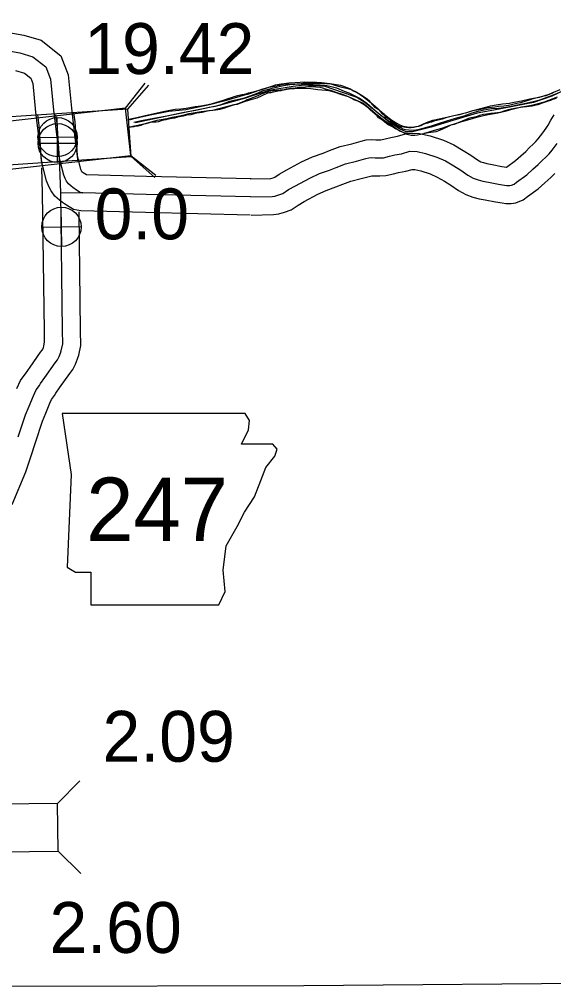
# Model space of a CAD drawing. Extents: x -83719 to 153526, y -11835 to 11446.
# Drawn here: x -1341.3 to -1193.4, y -29.8 to 238 of the extents above; entities that cross this region are included whole.
import ezdxf

# ---------------------------------------------------------------- set-up
doc = ezdxf.new("R2010")
doc.units = 0
for name, color, linetype in [('Level 10', 7, 'Continuous'), ('Level 2', 7, 'Continuous'), ('Level 20', 7, 'Continuous'), ('Level 21', 7, 'Continuous'), ('Level 25', 7, 'Continuous'), ('Level 26', 7, 'Continuous'), ('Level 58', 7, 'Continuous'), ('Level 59', 7, 'Continuous'), ('Level 9', 7, 'Continuous')]:
    doc.layers.add(name, color=color, linetype=linetype)

msp = doc.modelspace()

# ---------------------------------------------------------------- linework, layer by layer
at = {"layer": 'Level 10'}
for points in [[(-1364.45, 238.05), (-1340.09, 233.63), (-1335.27, 232.25), (-1329.85, 227.95), (-1327.78, 222.66), (-1326.9, 213.41), (-1325.93, 205.24), (-1325.18, 198.7)], [(-1342.37, 223.88), (-1339.93, 223.18), (-1338.17, 221.79), (-1337.6, 220.32), (-1336.85, 212.35), (-1335.86, 204.08), (-1335.14, 197.78)], [(-1277.17, 193.85), (-1306.13, 194.52), (-1322.78, 194.95), (-1322.78, 194.96), (-1323.66, 195.54), (-1323.86, 195.69), (-1323.95, 195.77), (-1324, 195.84), (-1324.16, 196.13), (-1324.31, 196.49), (-1325.27, 200.31), (-1325.89, 209.67), (-1326.24, 212.25)], [(-1277.41, 183.85), (-1306.38, 184.53), (-1324.28, 184.99), (-1326.37, 185.37), (-1328.27, 186.6), (-1329.4, 187.35), (-1330.19, 187.93), (-1331.51, 189.12), (-1332.52, 190.58), (-1333.16, 191.76), (-1333.81, 193.28), (-1335.19, 198.74), (-1335.85, 208.67), (-1336.24, 211.56)], [(-1277.4, 193.85), (-1271.81, 193.97), (-1271.7, 193.99), (-1271.01, 194.19), (-1270.64, 194.32), (-1269.4, 195.17), (-1267.24, 196.34), (-1263.2, 198.56), (-1260.15, 199.97), (-1257.2, 200.98), (-1255.46, 201.71), (-1252.53, 202.81), (-1249.23, 203.61), (-1246.7, 204.31), (-1245.33, 204.65), (-1243.84, 204.76), (-1242.61, 204.67), (-1241.8, 204.67), (-1241.23, 204.7), (-1240.04, 204.98), (-1238.45, 205.37), (-1236.64, 205.71), (-1233.78, 206.53), (-1230.58, 206.39), (-1227.59, 205.75), (-1223.92, 204.59), (-1221.07, 203.26), (-1218.47, 201.76), (-1216.36, 200.44), (-1214.51, 199.16), (-1213.56, 198.63), (-1212.82, 198.36), (-1211.93, 198.13), (-1210.44, 197.86), (-1207.76, 197.31), (-1206.44, 197.11), (-1203.94, 198.94), (-1202.44, 200.26), (-1201.12, 201.43), (-1200.07, 202.51), (-1199.03, 203.5), (-1198.28, 204.21), (-1197.71, 204.91), (-1196.41, 206.64), (-1195.44, 207.93), (-1194.92, 208.71), (-1194.2, 210.13), (-1193.27, 211.63)], [(-1342.04, 135.83), (-1340.98, 138.04), (-1339.96, 139.37), (-1339.68, 139.88), (-1338.36, 141.73), (-1335.45, 145.87), (-1335, 146.47), (-1334.88, 146.7), (-1334.69, 147.2), (-1334.59, 147.53), (-1334.33, 148.73), (-1334.36, 151.78), (-1334.89, 189.98), (-1335.14, 196.89)], [(-1277.18, 183.85), (-1270.92, 183.98), (-1269.5, 184.21), (-1267.94, 184.67), (-1266.07, 185.33), (-1264.17, 186.63), (-1262.45, 187.56), (-1258.68, 189.63), (-1256.4, 190.69), (-1253.67, 191.63), (-1251.79, 192.4), (-1249.57, 193.24), (-1246.72, 193.93), (-1244.15, 194.64), (-1243.78, 194.73), (-1242.98, 194.68), (-1241.53, 194.67), (-1239.83, 194.77), (-1237.72, 195.25), (-1236.33, 195.6), (-1234.35, 195.96), (-1232.59, 196.47), (-1231.85, 196.44), (-1230.15, 196.07), (-1227.56, 195.25), (-1225.69, 194.38), (-1223.62, 193.19), (-1221.86, 192.08), (-1219.78, 190.65), (-1217.75, 189.52), (-1215.79, 188.8), (-1214.06, 188.36), (-1212.34, 188.04), (-1209.52, 187.47), (-1207.69, 187.19), (-1206.65, 187.04), (-1205.16, 187.08), (-1203.83, 187.23), (-1201.82, 188.07), (-1200.67, 188.94), (-1197.69, 191.13), (-1195.81, 192.77), (-1194.2, 194.21), (-1193.04, 195.39)], [(-1343.29, 103.66), (-1339.58, 112.77), (-1338.2, 116.92), (-1336.87, 120.85), (-1334.96, 126.79), (-1334.04, 128.98), (-1332.89, 131.78), (-1332.42, 132.77), (-1331.58, 133.86), (-1331.2, 134.55), (-1330.19, 135.97), (-1327.37, 139.98), (-1326.56, 141.06), (-1325.75, 142.56), (-1325.21, 144), (-1324.91, 145.01), (-1324.31, 147.68), (-1324.36, 151.9), (-1324.81, 184.72)]]:
    msp.add_lwpolyline(points, dxfattribs=at)
at = {"layer": 'Level 2'}
for points in [[(-1188.22, 219.49), (-1193.88, 216.8), (-1198.99, 215), (-1209.97, 212.91), (-1214.57, 212.06), (-1222.24, 209.75), (-1227.33, 208.22), (-1232.5, 206.88), (-1234.26, 206.94), (-1236.08, 207.76), (-1238.53, 209.3), (-1245.71, 215.02), (-1247.92, 216.4), (-1248.86, 216.78), (-1256.63, 219.42), (-1258, 219.55), (-1260.07, 219.63), (-1262.47, 219.83), (-1265.53, 219.45), (-1272.23, 218.31), (-1277.97, 216.54)], [(-1277.68, 216.73), (-1276.17, 217.3), (-1275.06, 217.83), (-1273.84, 218.33), (-1272.38, 218.7), (-1270.92, 219.07), (-1269.77, 219.37), (-1268.24, 219.68), (-1266.48, 219.99), (-1263.66, 220.16), (-1262.22, 220.1), (-1260.02, 220.03), (-1258.02, 219.91), (-1256.68, 219.81), (-1255.41, 219.55), (-1253.56, 219.06), (-1251.44, 218.15), (-1250.13, 217.68), (-1248.77, 217.01), (-1246.95, 216.13), (-1245.12, 214.87), (-1243.51, 213.45), (-1241.7, 211.89), (-1241.22, 211.47), (-1240.27, 210.73), (-1239.39, 210.12), (-1238.1, 209.41), (-1237.39, 208.93), (-1236.51, 208.45), (-1235.8, 208.11), (-1235.12, 207.76), (-1234.38, 207.54), (-1233.48, 207.43), (-1232.21, 207.4), (-1230.92, 207.53), (-1229.56, 207.9), (-1227.18, 208.57), (-1225.56, 209.11), (-1222.99, 209.94), (-1220.61, 210.71), (-1218.19, 211.37), (-1215.95, 212.17), (-1214.3, 212.58), (-1212.74, 212.95), (-1210.62, 213.34), (-1208.62, 213.46), (-1206.56, 213.71), (-1205.14, 213.99), (-1202.98, 214.44), (-1201.59, 214.71), (-1199.07, 215.25), (-1197.22, 215.73), (-1195.14, 216.45), (-1193.46, 217.16), (-1191.68, 217.88)], [(-1309.2, 209.45), (-1299.09, 211.64), (-1285.9, 214.25), (-1277.97, 216.54)], [(-1297.95, 211.87), (-1295.69, 212.31), (-1294.09, 212.64), (-1292.49, 212.94), (-1288.76, 213.71), (-1287.03, 213.98), (-1285.43, 214.48), (-1283.07, 215.42), (-1281.97, 215.69), (-1281.01, 215.86), (-1279.41, 216.23), (-1278.68, 216.43), (-1277.68, 216.73)], [(-1309.68, 209.56), (-1307.54, 209.99), (-1305.14, 210.5), (-1302.54, 210.93), (-1300.51, 211.33), (-1297.95, 211.87)], [(-1136.66, -28.88), (-1174.76, -28.9), (-1262.54, -29.61)], [(-1262.54, -29.61), (-1343.7, -29.84)]]:
    msp.add_lwpolyline(points, dxfattribs=at)
at = {"layer": 'Level 20'}
for p, q in [((-1311.96, 213.45), (-1306.48, 220.34)), ((-1311.3, 213.21), (-1305.5, 219.83)), ((-1310.48, 200.34), (-1303.59, 194.86)), ((-1310.42, 200.04), (-1303.8, 194.24)), ((-1330.76, 20.89), (-1324.61, 27.18)), ((-1330.61, 7.69), (-1324.31, 1.54))]:
    msp.add_line(p, q, dxfattribs=at)
for points in [[(-1349.82, 195.87), (-1310.48, 200.34), (-1311.96, 213.45), (-1351.31, 208.98)], [(-1311.3, 213.21), (-1350.81, 210.58), (-1349.93, 197.41), (-1310.42, 200.04)], [(-1330.76, 20.89), (-1370.36, 20.43), (-1370.2, 7.23), (-1330.61, 7.69)]]:
    msp.add_lwpolyline(points, close=True, dxfattribs=at)
at = {"layer": 'Level 21'}
msp.add_lwpolyline([(-1329.49, 128.9), (-1326.95, 111.98), (-1328.08, 86.32), (-1325.82, 84.91), (-1321.59, 84.91), (-1321.59, 75.89), (-1286.06, 75.89), (-1284.37, 79.55), (-1284.94, 85.48), (-1284.09, 92.24), (-1280.99, 97.6), (-1279.02, 101.55), (-1276.2, 105.78), (-1274.5, 110.29), (-1273.09, 113.95), (-1270.56, 117.06), (-1269.99, 119.03), (-1271.12, 120.44), (-1279.86, 120.44), (-1277.89, 124.39), (-1277.61, 126.93), (-1278.78, 128.87)], close=True, dxfattribs=at)
at = {"layer": 'Level 26'}
for p, q in [((-1330.63, 200), (-1330.89, 210.85)), ((-1330.74, 198.37), (-1330.74, 209.2)), ((-1336.18, 205.3), (-1325.34, 205.55)), ((-1336.16, 203.78), (-1325.33, 203.78)), ((-1329.54, 175.15), (-1329.79, 186)), ((-1335.09, 180.45), (-1324.24, 180.7))]:
    msp.add_line(p, q, dxfattribs=at)
for centre, radius in [((-1330.76, 205.43), 5.43), ((-1330.74, 203.78), 5.42), ((-1329.66, 180.58), 5.43)]:
    msp.add_circle(centre, radius, dxfattribs=at)
at = {"layer": 'Level 59'}
for points in [[(-1364.89, 233.04), (-1341.23, 228.76), (-1337.6, 227.71), (-1334.01, 224.87), (-1332.69, 221.49), (-1331.87, 212.88), (-1330.89, 204.66), (-1330.16, 198.18)], [(-1277.29, 188.85), (-1306.25, 189.53), (-1323.76, 189.98), (-1324.5, 190.11), (-1325.53, 190.78), (-1326.53, 191.45), (-1327.03, 191.81), (-1327.73, 192.45), (-1328.26, 193.21), (-1328.66, 193.95), (-1329.06, 194.88), (-1330.23, 199.52), (-1330.87, 209.17), (-1331.2, 211.59)], [(-1277.29, 188.85), (-1271.36, 188.98), (-1270.6, 189.1), (-1269.48, 189.43), (-1268.35, 189.82), (-1266.78, 190.9), (-1264.85, 191.95), (-1260.94, 194.09), (-1258.27, 195.33), (-1255.44, 196.31), (-1253.62, 197.05), (-1251.05, 198.02), (-1247.97, 198.77), (-1245.43, 199.47), (-1244.53, 199.7), (-1243.83, 199.75), (-1242.8, 199.68), (-1241.67, 199.67), (-1240.53, 199.73), (-1238.88, 200.11), (-1237.39, 200.49), (-1235.5, 200.84), (-1233.18, 201.5), (-1231.22, 201.41), (-1228.87, 200.91), (-1225.74, 199.92), (-1223.38, 198.82), (-1221.04, 197.47), (-1219.11, 196.26), (-1217.14, 194.91), (-1215.65, 194.08), (-1214.31, 193.58), (-1213, 193.24), (-1211.39, 192.95), (-1208.64, 192.39), (-1206.97, 192.13), (-1206.37, 192.05), (-1205.5, 192.07), (-1205.1, 192.12), (-1204.34, 192.44), (-1203.66, 192.96), (-1200.82, 195.03), (-1199.12, 196.51), (-1197.66, 197.82), (-1196.56, 198.95), (-1195.58, 199.88), (-1194.61, 200.81), (-1193.77, 201.83), (-1192.42, 203.63)], [(-1341.62, 122.42), (-1339.66, 128.53), (-1338.66, 130.9), (-1337.46, 133.81), (-1336.7, 135.41), (-1335.77, 136.61), (-1335.44, 137.21), (-1334.27, 138.85), (-1331.41, 142.93), (-1330.78, 143.76), (-1330.32, 144.63), (-1329.95, 145.6), (-1329.75, 146.27), (-1329.32, 148.2), (-1329.36, 151.84), (-1329.89, 190.11), (-1330.23, 199.52)], [(-1329.89, 190.11), (-1323.76, 189.98)]]:
    msp.add_lwpolyline(points, dxfattribs=at)
at = {"layer": 'Level 9'}
for points in [[(-1277.88, 217.66), (-1276.26, 218.06), (-1275.24, 218.32), (-1274.15, 218.65), (-1273.02, 219.02), (-1272.3, 219.27), (-1271.47, 219.52), (-1270.38, 219.95), (-1268.86, 220.23), (-1268.03, 220.32), (-1266.73, 220.45), (-1264.93, 220.53), (-1263.6, 220.63), (-1262.44, 220.7), (-1260.67, 220.68), (-1259.04, 220.62), (-1257.7, 220.59), (-1256.8, 220.48), (-1255.39, 220.25), (-1253.68, 219.76), (-1252.07, 219.3), (-1250.76, 219), (-1249.48, 218.6), (-1247.9, 217.84), (-1246, 216.59), (-1243.89, 214.94), (-1242.83, 214), (-1240.85, 212.25), (-1240.23, 211.76), (-1240.09, 211.6), (-1238.56, 210.4), (-1237.75, 209.89), (-1236.97, 209.38), (-1236.16, 208.93), (-1235.31, 208.59), (-1234.51, 208.41), (-1233.34, 208.2), (-1232.54, 208.19), (-1231.57, 208.35), (-1230.85, 208.5), (-1229.46, 209.11), (-1228.57, 209.5), (-1226.89, 210.08), (-1225.07, 210.52), (-1222.58, 211.06), (-1220.2, 211.62), (-1217.42, 212.29), (-1216.06, 212.7), (-1213.95, 213.22), (-1212.19, 213.7), (-1210.9, 214.07), (-1209.31, 214.38), (-1207.52, 214.66), (-1205.59, 214.87), (-1204.37, 215.11), (-1202.31, 215.5), (-1200.03, 216.06), (-1197.94, 216.41), (-1196.09, 216.86), (-1194.63, 217.33), (-1192.66, 218.15)], [(-1253.61, 219.93), (-1254.75, 220.07), (-1256.28, 220.19), (-1257.42, 220.26), (-1259.18, 220.25), (-1260.55, 220.25), (-1262.88, 220.25), (-1263.74, 220.13), (-1264.54, 220.08), (-1265.14, 220.03), (-1265.54, 219.99), (-1266.01, 219.97), (-1266.41, 220), (-1266.57, 220.03), (-1267.18, 220.08), (-1267.64, 220.06), (-1268.67, 219.9), (-1269.27, 219.75), (-1269.95, 219.66)], [(-1191.72, 218.5), (-1193.47, 217.75), (-1193.93, 217.5), (-1194.45, 217.29), (-1195.54, 216.89), (-1196.11, 216.78), (-1197.36, 216.38), (-1199.12, 216), (-1199.88, 215.75), (-1202.56, 214.97), (-1203.58, 214.75), (-1204.28, 214.56), (-1205.04, 214.38), (-1205.93, 214.19), (-1207.23, 213.99), (-1208.63, 213.88), (-1209.72, 213.72), (-1211.42, 213.54), (-1212.34, 213.38), (-1213.57, 213.12), (-1214.7, 212.92), (-1215.86, 212.69), (-1217.48, 212.18), (-1218.6, 211.89), (-1219.59, 211.59), (-1221.05, 211.32), (-1223.2, 210.73), (-1224.26, 210.37), (-1225.35, 210.11), (-1226.58, 209.84), (-1227.24, 209.59), (-1227.73, 209.48), (-1228.26, 209.33), (-1229.06, 209.11), (-1229.48, 208.9), (-1230.21, 208.58), (-1230.77, 208.4), (-1231.33, 208.25), (-1232.09, 208.1), (-1232.83, 208.04), (-1233.53, 208.03), (-1234.29, 208.07), (-1235.5, 208.28), (-1236.2, 208.49), (-1236.88, 208.84), (-1237.59, 209.32), (-1238.27, 209.74), (-1238.68, 210.1), (-1239.77, 210.87), (-1240.25, 211.39), (-1240.66, 211.78), (-1241.24, 212.43), (-1241.65, 212.86), (-1242.16, 213.18), (-1242.78, 213.66), (-1243.49, 214.38), (-1244.15, 215.13), (-1244.32, 215.29), (-1245.04, 215.91), (-1245.85, 216.49), (-1246.39, 216.84), (-1247.34, 217.39), (-1248.32, 217.93), (-1249, 218.28), (-1249.85, 218.76), (-1250.59, 219.1), (-1251.46, 219.45), (-1252.3, 219.69), (-1253.61, 219.93)], [(-1310.98, 210.37), (-1309.73, 210.69), (-1308.77, 210.89), (-1306.47, 211.43), (-1304.37, 211.86), (-1302.34, 212.37), (-1301.01, 212.6), (-1299.18, 212.97), (-1298.15, 213.17), (-1296.62, 213.31), (-1295.19, 213.47), (-1292.66, 213.88), (-1291.06, 214.08), (-1289.5, 214.41), (-1287.83, 214.78), (-1286.03, 215.32), (-1284.3, 215.85), (-1283.54, 216.16), (-1282.31, 216.52), (-1281.84, 216.69), (-1280.81, 216.96), (-1279.74, 217.19), (-1279.08, 217.36), (-1278.55, 217.46), (-1277.88, 217.66)], [(-1278.11, 217.34), (-1284.73, 215.42), (-1288.66, 214.39), (-1295.26, 212.97), (-1299.92, 212.51), (-1305.11, 211.49), (-1309.98, 210.36), (-1310.96, 210.14)], [(-1278.11, 217.34), (-1275.95, 218.11), (-1274.21, 218.74), (-1272.24, 219.27), (-1269.95, 219.66)], [(-1272.63, 217.63), (-1275.59, 216.24), (-1276.93, 215.82), (-1277.91, 215.54)], [(-1277.58, 216.03), (-1275.2, 216.99), (-1274.31, 217.38), (-1272.96, 217.92), (-1272.27, 218.13), (-1271.04, 218.33), (-1270.07, 218.43), (-1269.14, 218.48), (-1267.61, 218.62), (-1266.12, 218.86), (-1265.12, 218.92), (-1263.16, 218.97), (-1261.86, 218.98), (-1260.59, 218.91), (-1258.68, 218.66), (-1256.51, 218.45), (-1255.64, 218.34), (-1254.27, 217.97), (-1252.18, 217.23), (-1250.33, 216.64), (-1248.61, 215.98), (-1246.18, 214.81), (-1244.14, 213.2), (-1242.06, 211.41), (-1242.02, 211.42), (-1240.9, 210.54), (-1239.2, 209.39), (-1238.05, 208.58), (-1236.45, 207.49), (-1235.13, 206.82), (-1234.26, 206.53)], [(-1192.69, 216.13), (-1193.68, 215.81), (-1194.28, 215.59), (-1194.9, 215.37), (-1196.55, 214.8), (-1197.74, 214.36), (-1198.6, 214.21), (-1199.33, 214.02), (-1200.16, 213.93), (-1200.93, 213.85), (-1201.86, 213.72), (-1202.55, 213.64), (-1203.02, 213.56), (-1203.71, 213.44), (-1204.18, 213.36), (-1205.17, 213.17), (-1205.97, 212.98), (-1206.6, 212.77), (-1207.16, 212.58), (-1207.42, 212.48), (-1207.88, 212.37), (-1208.25, 212.26), (-1208.98, 212.14), (-1209.74, 212.02), (-1210.74, 211.96), (-1212, 211.79), (-1212.83, 211.67), (-1213.89, 211.41), (-1214.88, 211.08), (-1216.7, 210.7), (-1217, 210.56), (-1217.59, 210.34), (-1220.26, 209.21), (-1220.92, 208.95), (-1221.85, 208.7), (-1222.93, 208.2), (-1223.99, 207.74), (-1225.01, 207.28), (-1226, 206.89), (-1228.69, 206.52), (-1229.32, 206.37), (-1230.28, 206.14), (-1231.07, 205.95), (-1231.87, 205.86), (-1232.8, 205.87), (-1233.24, 205.96), (-1233.97, 206.14), (-1234.62, 206.43), (-1235.23, 206.81), (-1236.03, 207.09), (-1236.54, 207.41), (-1237.39, 207.83), (-1237.86, 208.21), (-1238.54, 208.56), (-1239.25, 208.81), (-1241.08, 210.27), (-1241.9, 210.78), (-1242.25, 211.31), (-1243.44, 212.38), (-1244.22, 212.96), (-1244.71, 213.55), (-1245.52, 214.06), (-1246.33, 214.61), (-1247.08, 215.12), (-1247.62, 215.37), (-1248.7, 215.78), (-1249.24, 216.1), (-1249.98, 216.52), (-1250.83, 216.86), (-1252.14, 217.33), (-1253.32, 217.7), (-1254.39, 218.04), (-1255.2, 218.35), (-1256.61, 218.75), (-1257.32, 218.96), (-1258.12, 219.14), (-1259.26, 219.31), (-1260.29, 219.32), (-1261.49, 219.36), (-1262.22, 219.3), (-1263.22, 219.21), (-1263.92, 219.13), (-1264.95, 219.03), (-1265.91, 218.87), (-1266.44, 218.86), (-1267.07, 218.74), (-1267.44, 218.67), (-1267.97, 218.49), (-1268.96, 218.29), (-1269.42, 218.21), (-1270.15, 218.06), (-1270.58, 217.95), (-1271.05, 217.87), (-1271.68, 217.72), (-1272.31, 217.67), (-1272.57, 217.63), (-1272.63, 217.63)], [(-1311.23, 208.2), (-1309.43, 208.55), (-1307.7, 208.92), (-1306.14, 209.29), (-1304.51, 209.73), (-1303.17, 210.13), (-1302.08, 210.33), (-1300.51, 210.63), (-1298.98, 211), (-1297.95, 211.14), (-1296.55, 211.44), (-1295.32, 211.71), (-1294.32, 211.94), (-1292.69, 212.24), (-1290.96, 212.54), (-1289.53, 212.74), (-1288.7, 212.81), (-1287, 212.98), (-1285.77, 213.18), (-1284.4, 213.52), (-1283.47, 213.92), (-1282.3, 214.32), (-1281.07, 214.66), (-1279.71, 215.12), (-1278.74, 215.53), (-1278.21, 215.86), (-1277.58, 216.03)], [(-1277.91, 215.54), (-1278.78, 215.31), (-1280.11, 214.81), (-1281.07, 214.51), (-1281.94, 214.38), (-1284.34, 213.75), (-1287.9, 212.82), (-1288.83, 212.69), (-1289.6, 212.49), (-1290.67, 212.29), (-1291.46, 212.13), (-1292.2, 212.03), (-1292.9, 211.9), (-1293.86, 211.63), (-1295.09, 211.47), (-1295.99, 211.23), (-1296.96, 211.04), (-1297.83, 210.87), (-1298.39, 210.71), (-1299.06, 210.61), (-1300.16, 210.37), (-1300.79, 210.24), (-1301.39, 210.11), (-1302.09, 209.91), (-1302.85, 209.71), (-1303.49, 209.61), (-1304.02, 209.61), (-1304.62, 209.55), (-1305.35, 209.38), (-1306.28, 209.12), (-1306.88, 208.99), (-1307.68, 208.65), (-1308.48, 208.49), (-1308.98, 208.42), (-1309.68, 208.29), (-1310.41, 208.19), (-1310.7, 208.16)], [(-1229.34, 206.53), (-1228.79, 206.65), (-1226.38, 207.38), (-1224.33, 207.94), (-1222.09, 208.7), (-1220.57, 209.17), (-1218.16, 209.94), (-1215.87, 210.63), (-1214.65, 210.96), (-1212.8, 211.45), (-1211.54, 211.71), (-1209.32, 212.11), (-1207.99, 212.37), (-1206.47, 212.72), (-1205.54, 213.01), (-1204.85, 213.19), (-1203.36, 213.53), (-1202.33, 213.79), (-1201.07, 213.99), (-1199.55, 214.3), (-1197.66, 214.78), (-1195.91, 215.2), (-1192.28, 216.59)]]:
    msp.add_lwpolyline(points, dxfattribs=at)

# ---------------------------------------------------------------- texts
at = {"layer": 'Level 21'}
msp.add_text('247', height=17.6, dxfattribs=at).set_placement((-1322.82, 93.54))
at = {"layer": 'Level 25'}
for s, p in [('19.42', (-1323.38, 222.91)), ('0.0', (-1320.51, 177.13)), ('2.60', (-1333, -20.49))]:
    msp.add_text(s, height=14.08, dxfattribs=at).set_placement(p)
at = {"layer": 'Level 58'}
for s, p in [('0.0', (-1320.51, 177.13)), ('2.09', (-1318.32, 32.45))]:
    msp.add_text(s, height=14.08, dxfattribs=at).set_placement(p)

doc.saveas('drawing.dxf')
